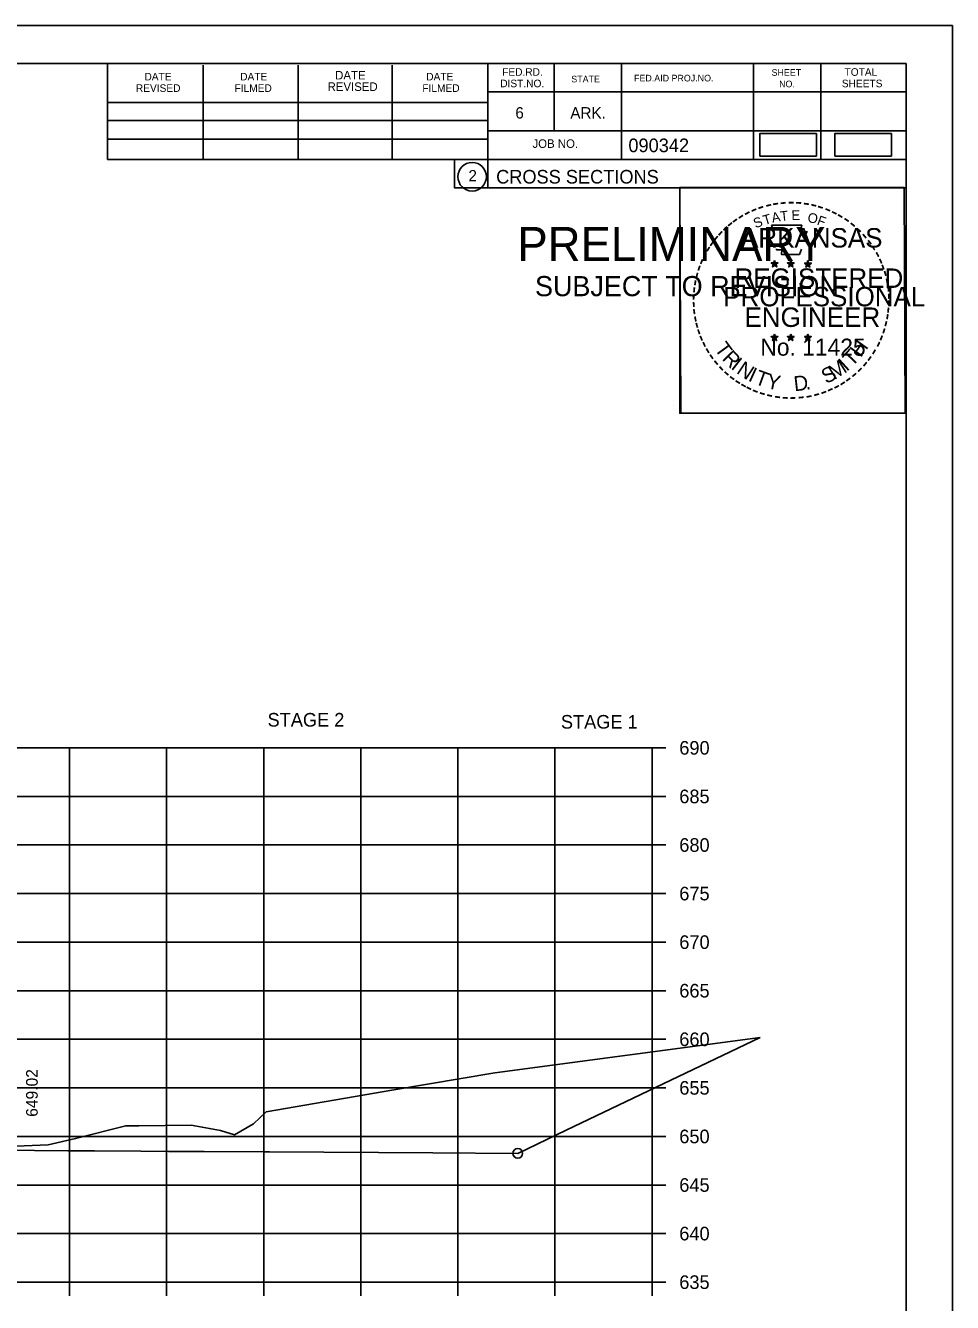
# Model space of a CAD drawing. Extents: x 1370515 to 1370849, y 383299 to 386073.
# Drawn here: x 1370753.3 to 1370848.7, y 384448 to 384579.5 of the extents above; entities that cross this region are included whole.
import ezdxf

# ---------------------------------------------------------------- set-up
doc = ezdxf.new("R2010")
doc.units = 0
for name, color, linetype in [('R_Axis', 7, 'Continuous'), ('R_Axis Annot', 7, 'Continuous'), ('R_Border', 7, 'Continuous'), ('R_Border PE', 7, 'Continuous'), ('R_Border Prem', 7, 'Continuous'), ('R_Detour', 7, 'Continuous'), ('R_Exist Surface', 7, 'Continuous'), ('R_Fin Surface', 7, 'Continuous'), ('R_Grid', 7, 'Continuous'), ('R_No Plot', 7, 'Continuous'), ('R_Xsect Elev', 7, 'Continuous')]:
    doc.layers.add(name, color=color, linetype=linetype)

msp = doc.modelspace()

# ---------------------------------------------------------------- linework, layer by layer
at = {"layer": 'R_Axis'}
for p, q in [((1370819.2, 384505.1), (1370816.4, 384505.1)), ((1370817.8, 384450.1), (1370817.8, 384505.1)), ((1370819.2, 384500.1), (1370816.4, 384500.1)), ((1370819.2, 384495.1), (1370816.4, 384495.1)), ((1370819.2, 384490.1), (1370816.4, 384490.1)), ((1370819.2, 384485.1), (1370816.4, 384485.1)), ((1370819.2, 384480.1), (1370816.4, 384480.1)), ((1370819.2, 384475.1), (1370816.4, 384475.1)), ((1370819.2, 384470.1), (1370816.4, 384470.1)), ((1370819.2, 384465.1), (1370816.4, 384465.1)), ((1370819.2, 384460.1), (1370816.4, 384460.1)), ((1370819.2, 384455.1), (1370816.4, 384455.1)), ((1370757.8, 384448.7), (1370757.8, 384451.5)), ((1370767.8, 384448.7), (1370767.8, 384451.5)), ((1370777.8, 384448.7), (1370777.8, 384451.5)), ((1370787.8, 384448.7), (1370787.8, 384451.5)), ((1370797.8, 384448.7), (1370797.8, 384451.5)), ((1370807.8, 384448.7), (1370807.8, 384451.5)), ((1370817.8, 384448.7), (1370817.8, 384451.5)), ((1370537.8, 384450.1), (1370817.8, 384450.1)), ((1370819.2, 384450.1), (1370816.4, 384450.1))]:
    msp.add_line(p, q, dxfattribs=at)
at = {"layer": 'R_Border'}
for p, q in [((1370527.8, 384575.56), (1370843.98, 384575.56)), ((1370761.72, 384565.68), (1370761.72, 384575.56)), ((1370771.58, 384565.68), (1370771.58, 384575.36)), ((1370781.34, 384565.68), (1370781.34, 384575.36)), ((1370791.02, 384565.68), (1370791.02, 384575.36)), ((1370800.88, 384575.56), (1370800.88, 384562.76)), ((1370807.72, 384575.56), (1370807.72, 384568.62)), ((1370814.66, 384575.56), (1370814.66, 384565.68)), ((1370828.24, 384575.56), (1370828.24, 384565.68)), ((1370835.18, 384575.56), (1370835.18, 384565.68)), ((1370843.98, 384370.1), (1370843.98, 384575.56)), ((1370843.98, 384572.62), (1370800.88, 384572.62)), ((1370843.98, 384572.64), (1370843.98, 384572.64)), ((1370761.72, 384571.54), (1370800.88, 384571.54)), ((1370761.72, 384569.68), (1370800.88, 384569.68)), ((1370761.72, 384565.68), (1370761.72, 384567.74)), ((1370761.72, 384567.74), (1370800.88, 384567.74)), ((1370843.98, 384568.62), (1370800.88, 384568.62)), ((1370803.84, 384568.62), (1370843.98, 384568.62)), ((1370843.98, 384565.68), (1370761.72, 384565.68)), ((1370800.88, 384562.76), (1370843.98, 384562.76))]:
    msp.add_line(p, q, dxfattribs=at)
msp.add_circle((1370799.27, 384563.89), 1.47, dxfattribs=at)
at = {"layer": 'R_Border PE'}
for p, q in [((1370830.07, 384555.01), (1370830.42, 384554.9)), ((1370830.07, 384555.01), (1370830.32, 384554.97)), ((1370830.07, 384555.01), (1370830.3, 384554.89)), ((1370830.2, 384554.61), (1370830.42, 384554.9)), ((1370830.2, 384554.61), (1370830.33, 384554.85)), ((1370830.2, 384554.61), (1370830.41, 384554.82)), ((1370830.42, 384555.27), (1370830.37, 384555.02)), ((1370830.63, 384554.61), (1370830.41, 384554.82)), ((1370830.42, 384554.9), (1370830.42, 384555.27)), ((1370830.42, 384555.27), (1370830.46, 384555.02)), ((1370830.76, 384555.01), (1370830.42, 384554.9)), ((1370830.63, 384554.61), (1370830.42, 384554.9)), ((1370830.76, 384555.01), (1370830.48, 384554.96)), ((1370830.63, 384554.61), (1370830.49, 384554.9)), ((1370830.76, 384555.01), (1370830.56, 384554.91)), ((1370831.74, 384555.01), (1370832.09, 384554.9)), ((1370831.74, 384555.01), (1370831.99, 384554.97)), ((1370831.74, 384555.01), (1370831.97, 384554.89)), ((1370831.87, 384554.61), (1370832.09, 384554.9)), ((1370831.87, 384554.61), (1370832, 384554.85)), ((1370831.87, 384554.61), (1370832.08, 384554.82)), ((1370832.09, 384555.27), (1370832.04, 384555.02)), ((1370832.3, 384554.61), (1370832.08, 384554.82)), ((1370832.09, 384554.9), (1370832.09, 384555.27)), ((1370832.09, 384555.27), (1370832.13, 384555.02)), ((1370832.43, 384555.01), (1370832.09, 384554.9)), ((1370832.3, 384554.61), (1370832.09, 384554.9)), ((1370832.43, 384555.01), (1370832.15, 384554.96)), ((1370832.3, 384554.61), (1370832.16, 384554.9)), ((1370832.43, 384555.01), (1370832.23, 384554.91)), ((1370833.5, 384555), (1370833.85, 384554.89)), ((1370833.5, 384555), (1370833.75, 384554.96)), ((1370833.5, 384555), (1370833.74, 384554.88)), ((1370833.63, 384554.59), (1370833.85, 384554.89)), ((1370833.63, 384554.59), (1370833.76, 384554.84)), ((1370833.63, 384554.59), (1370833.85, 384554.81)), ((1370833.85, 384555.26), (1370833.81, 384555)), ((1370833.85, 384554.89), (1370833.85, 384555.26)), ((1370833.85, 384555.26), (1370833.9, 384555.01)), ((1370834.2, 384555), (1370833.85, 384554.89)), ((1370834.06, 384554.59), (1370833.85, 384554.89)), ((1370834.06, 384554.59), (1370833.85, 384554.81)), ((1370834.2, 384555), (1370833.91, 384554.95)), ((1370834.06, 384554.59), (1370833.93, 384554.88)), ((1370834.2, 384555), (1370833.99, 384554.9)), ((1370830.06, 384547.44), (1370830.41, 384547.33)), ((1370830.06, 384547.44), (1370830.32, 384547.4)), ((1370830.06, 384547.44), (1370830.3, 384547.32)), ((1370830.2, 384547.03), (1370830.41, 384547.33)), ((1370830.2, 384547.03), (1370830.32, 384547.28)), ((1370830.2, 384547.03), (1370830.41, 384547.25)), ((1370830.41, 384547.69), (1370830.37, 384547.44)), ((1370830.41, 384547.33), (1370830.41, 384547.69)), ((1370830.41, 384547.69), (1370830.46, 384547.44)), ((1370830.76, 384547.44), (1370830.41, 384547.33)), ((1370830.62, 384547.03), (1370830.41, 384547.33)), ((1370830.62, 384547.03), (1370830.41, 384547.25)), ((1370830.76, 384547.44), (1370830.47, 384547.39)), ((1370830.62, 384547.03), (1370830.49, 384547.32)), ((1370830.76, 384547.44), (1370830.55, 384547.34)), ((1370831.73, 384547.44), (1370832.08, 384547.33)), ((1370831.73, 384547.44), (1370831.98, 384547.4)), ((1370831.73, 384547.44), (1370831.97, 384547.32)), ((1370831.86, 384547.03), (1370832.08, 384547.33)), ((1370831.86, 384547.03), (1370831.99, 384547.28)), ((1370831.86, 384547.03), (1370832.08, 384547.25)), ((1370832.08, 384547.69), (1370832.04, 384547.44)), ((1370832.08, 384547.33), (1370832.08, 384547.69)), ((1370832.08, 384547.69), (1370832.13, 384547.44)), ((1370832.43, 384547.44), (1370832.08, 384547.33)), ((1370832.29, 384547.03), (1370832.08, 384547.33)), ((1370832.29, 384547.03), (1370832.08, 384547.25)), ((1370832.43, 384547.44), (1370832.14, 384547.39)), ((1370832.29, 384547.03), (1370832.16, 384547.32)), ((1370832.43, 384547.44), (1370832.22, 384547.34)), ((1370833.5, 384547.43), (1370833.85, 384547.32)), ((1370833.5, 384547.43), (1370833.75, 384547.39)), ((1370833.5, 384547.43), (1370833.74, 384547.31)), ((1370833.63, 384547.02), (1370833.85, 384547.32)), ((1370833.63, 384547.02), (1370833.76, 384547.27)), ((1370833.63, 384547.02), (1370833.85, 384547.24)), ((1370833.85, 384547.68), (1370833.81, 384547.43)), ((1370833.85, 384547.32), (1370833.85, 384547.68)), ((1370833.85, 384547.68), (1370833.9, 384547.43)), ((1370834.19, 384547.43), (1370833.85, 384547.32)), ((1370834.06, 384547.02), (1370833.85, 384547.32)), ((1370834.06, 384547.02), (1370833.85, 384547.24)), ((1370834.19, 384547.43), (1370833.91, 384547.38)), ((1370834.06, 384547.02), (1370833.92, 384547.31)), ((1370834.19, 384547.43), (1370833.99, 384547.33))]:
    msp.add_line(p, q, dxfattribs=at)
for points in [[(1370830.11, 384558.89), (1370830.38, 384558.06)], [(1370833.62, 384557.97), (1370833.76, 384558.25), (1370833.08, 384558.23), (1370833.22, 384558.89), (1370830.11, 384558.89)], [(1370830.6, 384556.47), (1370830.6, 384556.38), (1370831.16, 384556.36), (1370831.11, 384555.89), (1370832.98, 384555.89), (1370833.18, 384556.43)], [(1370830.42, 384555.27), (1370830.63, 384554.61), (1370830.07, 384555.01), (1370830.76, 384555.01), (1370830.2, 384554.61), (1370830.42, 384555.27)], [(1370832.09, 384555.27), (1370832.3, 384554.61), (1370831.74, 384555.01), (1370832.43, 384555.01), (1370831.87, 384554.61), (1370832.09, 384555.27)], [(1370833.85, 384555.26), (1370834.06, 384554.59), (1370833.5, 384555), (1370834.2, 384555), (1370833.63, 384554.59), (1370833.85, 384555.26)], [(1370830.41, 384547.69), (1370830.62, 384547.03), (1370830.06, 384547.44), (1370830.76, 384547.44), (1370830.2, 384547.03), (1370830.41, 384547.69)], [(1370832.08, 384547.69), (1370832.29, 384547.03), (1370831.73, 384547.44), (1370832.43, 384547.44), (1370831.86, 384547.03), (1370832.08, 384547.69)], [(1370833.85, 384547.68), (1370834.06, 384547.02), (1370833.5, 384547.43), (1370834.19, 384547.43), (1370833.63, 384547.02), (1370833.85, 384547.68)]]:
    msp.add_lwpolyline(points, dxfattribs=at)
for centre, radius in [((1370830.41, 384554.9), 0.172), ((1370830.41, 384554.9), 0.145), ((1370830.41, 384554.9), 0.116), ((1370830.41, 384554.9), 0.0991), ((1370830.41, 384554.9), 0.0747), ((1370830.41, 384554.9), 0.0495), ((1370830.41, 384554.9), 0.0296), ((1370832.08, 384554.9), 0.172), ((1370832.08, 384554.9), 0.145), ((1370832.08, 384554.9), 0.116), ((1370832.08, 384554.9), 0.0991), ((1370832.08, 384554.9), 0.0747), ((1370832.08, 384554.9), 0.0495), ((1370832.08, 384554.9), 0.0296), ((1370833.85, 384554.89), 0.172), ((1370833.85, 384554.89), 0.145), ((1370833.85, 384554.89), 0.116), ((1370833.85, 384554.89), 0.0991), ((1370833.85, 384554.89), 0.0747), ((1370833.85, 384554.89), 0.0495), ((1370833.85, 384554.89), 0.0296), ((1370830.41, 384547.33), 0.172), ((1370830.41, 384547.33), 0.145), ((1370830.41, 384547.33), 0.116), ((1370830.41, 384547.33), 0.0991), ((1370830.41, 384547.33), 0.0747), ((1370830.41, 384547.33), 0.0495), ((1370830.41, 384547.33), 0.0296), ((1370832.08, 384547.33), 0.172), ((1370832.08, 384547.33), 0.145), ((1370832.08, 384547.33), 0.116), ((1370832.08, 384547.33), 0.0991), ((1370832.08, 384547.33), 0.0747), ((1370832.08, 384547.33), 0.0495), ((1370832.08, 384547.33), 0.0296), ((1370833.85, 384547.32), 0.172), ((1370833.85, 384547.32), 0.145), ((1370833.85, 384547.32), 0.116), ((1370833.85, 384547.32), 0.0991), ((1370833.85, 384547.32), 0.0747), ((1370833.85, 384547.32), 0.0495), ((1370833.85, 384547.32), 0.0296)]:
    msp.add_circle(centre, radius, dxfattribs=at)
at = {"layer": 'R_Detour'}
for points in [[(1370828.89, 384566.02), (1370834.73, 384566.02), (1370834.73, 384568.33), (1370828.89, 384568.33)], [(1370836.61, 384566.02), (1370842.45, 384566.02), (1370842.45, 384568.33), (1370836.61, 384568.33)]]:
    msp.add_lwpolyline(points, close=True, dxfattribs=at)
at = {"layer": 'R_Exist Surface'}
msp.add_lwpolyline([(1370747.33, 384463.89), (1370755.59, 384464.24), (1370758.43, 384464.88), (1370763.6, 384466.2), (1370764.93, 384466.2), (1370770.33, 384466.25), (1370773.37, 384465.7), (1370774.79, 384465.27), (1370776.76, 384466.39), (1370778.04, 384467.63), (1370791.22, 384469.88), (1370801.6, 384471.63), (1370828.92, 384475.28)], dxfattribs=at)
at = {"layer": 'R_Fin Surface'}
msp.add_lwpolyline([(1370747.31, 384463.73), (1370757.64, 384463.63), (1370757.72, 384463.63), (1370760.37, 384463.61), (1370765.16, 384463.58), (1370768.01, 384463.56), (1370771.67, 384463.54), (1370777.8, 384463.5), (1370778.17, 384463.5), (1370778.39, 384463.5), (1370795.23, 384463.4), (1370803.97, 384463.35), (1370808.96, 384465.74), (1370828.92, 384475.28)], dxfattribs=at)
at = {"layer": 'R_Grid'}
for p, q in [((1370537.8, 384505.1), (1370817.8, 384505.1)), ((1370757.8, 384450.1), (1370757.8, 384505.1)), ((1370767.8, 384450.1), (1370767.8, 384505.1)), ((1370777.8, 384450.1), (1370777.8, 384505.1)), ((1370787.8, 384450.1), (1370787.8, 384505.1)), ((1370797.8, 384450.1), (1370797.8, 384505.1)), ((1370807.8, 384450.1), (1370807.8, 384505.1)), ((1370817.8, 384450.1), (1370817.8, 384505.1)), ((1370537.8, 384500.1), (1370817.8, 384500.1)), ((1370537.8, 384495.1), (1370817.8, 384495.1)), ((1370537.8, 384490.1), (1370817.8, 384490.1)), ((1370537.8, 384485.1), (1370817.8, 384485.1)), ((1370537.8, 384480.1), (1370817.8, 384480.1)), ((1370537.8, 384475.1), (1370817.8, 384475.1)), ((1370537.8, 384470.1), (1370817.8, 384470.1)), ((1370537.8, 384465.1), (1370817.8, 384465.1)), ((1370537.8, 384460.1), (1370817.8, 384460.1)), ((1370537.8, 384455.1), (1370817.8, 384455.1)), ((1370537.8, 384450.1), (1370817.8, 384450.1))]:
    msp.add_line(p, q, dxfattribs=at)
at = {"layer": 'R_No Plot'}
for p, q in [((1370515.4, 384579.45), (1370848.73, 384579.45)), ((1370820.02, 384540.3), (1370820.02, 384540.3))]:
    msp.add_line(p, q, dxfattribs=at)
for points in [[(1370515.39, 384579.45), (1370848.73, 384579.45), (1370848.73, 384366.12), (1370515.39, 384366.12)], [(1370761.72, 384575.56), (1370761.72, 384565.68), (1370797.45, 384565.68), (1370797.45, 384562.76), (1370820.65, 384562.76), (1370820.65, 384539.54), (1370843.98, 384539.54), (1370843.98, 384370.1), (1370527.8, 384370.1), (1370527.8, 384575.56)], [(1370820.65, 384562.79), (1370843.75, 384562.79), (1370843.87, 384539.54), (1370820.77, 384539.54)]]:
    msp.add_lwpolyline(points, close=True, dxfattribs=at)
msp.add_circle((1370803.97, 384463.35), 0.5, dxfattribs=at)
msp.add_circle((1370803.97, 384463.35), 0.5, dxfattribs=at)

# ---------------------------------------------------------------- texts
at = {"layer": 'R_Axis Annot'}
for s, p in [('STAGE 2', (1370778.2, 384507.29)), ('STAGE 1', (1370808.41, 384507.08)), ('690', (1370820.6, 384504.4)), ('685', (1370820.6, 384499.4)), ('680', (1370820.6, 384494.4)), ('675', (1370820.6, 384489.4)), ('670', (1370820.6, 384484.4)), ('665', (1370820.6, 384479.4)), ('660', (1370820.6, 384474.4)), ('655', (1370820.6, 384469.4)), ('650', (1370820.6, 384464.4)), ('645', (1370820.6, 384459.4)), ('640', (1370820.6, 384454.4)), ('635', (1370820.6, 384449.4))]:
    msp.add_text(s, height=1.4, dxfattribs=at).set_placement(p)
at = {"layer": 'R_Border'}
for s, height, p in [('DATE', 0.782, (1370765.52, 384573.8)), ('DATE', 0.782, (1370775.38, 384573.8)), ('DATE', 0.879, (1370785.16, 384573.9)), ('DATE', 0.782, (1370794.54, 384573.8)), ('FED.RD.', 0.782, (1370802.36, 384574.28)), ('STATE', 0.684, (1370809.48, 384573.6)), ('FED.AID PROJ.NO.', 0.684, (1370815.94, 384573.7)), ('SHEET', 0.684, (1370830.1, 384574.28)), ('TOTAL', 0.782, (1370837.62, 384574.28)), ('REVISED', 0.782, (1370764.64, 384572.62)), ('FILMED', 0.782, (1370774.8, 384572.62)), ('REVISED', 0.879, (1370784.38, 384572.72)), ('FILMED', 0.782, (1370794.14, 384572.62)), ('DIST.NO.', 0.782, (1370802.16, 384573.1)), ('NO.', 0.684, (1370830.88, 384573.1)), ('SHEETS', 0.782, (1370837.34, 384573.1)), ('6', 1.17, (1370803.72, 384569.88)), ('ARK.', 1.172, (1370809.38, 384569.88)), ('JOB NO.', 0.879, (1370805.48, 384566.86)), ('090342', 1.4, (1370815.36, 384566.42)), ('2', 1.17, (1370798.89, 384563.41)), ('CROSS SECTIONS', 1.4, (1370801.74, 384563.19))]:
    msp.add_text(s, height=height, rotation=360, dxfattribs=at).set_placement(p)
at = {"layer": 'R_Border PE'}
for s, height, rotation, p in [('-', 1.6, 10.2193, (1370830.28, 384560.42)), ('-', 1.6, 5.8968, (1370831.01, 384560.53)), ('-', 1.6, 0.1862, (1370831.78, 384560.6)), ('-', 1.6, 357.743, (1370832.51, 384560.59)), ('-', 1.6, 352.1617, (1370833.25, 384560.53)), ('-', 1.6, 34.0636, (1370826.99, 384559.06)), ('-', 1.6, 28.7918, (1370827.59, 384559.43)), ('-', 1.6, 24.3072, (1370828.22, 384559.75)), ('-', 1.6, 19.1761, (1370828.86, 384560.02)), ('T', 1, 16.4036, (1370829.38, 384558.9)), ('-', 1.6, 13.6301, (1370829.61, 384560.26)), ('A', 1, 11.2132, (1370830.2, 384559.15)), ('T', 1, 6.0228, (1370831.05, 384559.32)), ('E', 1, 0.8323, (1370832.16, 384559.43)), ('O', 1, 350.4515, (1370833.76, 384559.22)), ('-', 1.6, 347.2049, (1370833.97, 384560.42)), ('F', 1, 340.0707, (1370834.71, 384558.99)), ('-', 1.6, 342.3362, (1370834.61, 384560.27)), ('-', 1.6, 337.8551, (1370835.34, 384560.04)), ('-', 1.6, 334.1211, (1370835.97, 384559.77)), ('-', 1.6, 329.6409, (1370836.55, 384559.49)), ('-', 1.6, 42.9622, (1370825.5, 384557.87)), ('-', 1.6, 38.9507, (1370825.94, 384558.29)), ('-', 1.6, 36.2317, (1370826.41, 384558.67)), ('ARKANSAS', 2, 360, (1370826.96, 384556.6)), ('S', 1, 21.594, (1370828.46, 384558.57)), ('-', 1.6, 325.8627, (1370837.19, 384559.13)), ('-', 1.6, 320.5297, (1370837.8, 384558.7)), ('-', 1.6, 315.5786, (1370838.4, 384558.21)), ('-', 1.6, 54.2325, (1370824.24, 384556.34)), ('-', 1.6, 50.6142, (1370824.65, 384556.91)), ('-', 1.6, 48.423, (1370825.06, 384557.39)), ('-', 1.6, 309.8797, (1370838.97, 384557.66)), ('-', 1.6, 306.6522, (1370839.5, 384557.06)), ('-', 1.6, 62.8713, (1370823.6, 384555.2)), ('-', 1.6, 58.0706, (1370823.92, 384555.81)), ('-', 1.4, 303.6753, (1370839.98, 384556.49)), ('-', 1.6, 299.6684, (1370840.3, 384555.89)), ('-', 1.6, 72.3945, (1370823.12, 384553.96)), ('-', 1.6, 67.7743, (1370823.34, 384554.59)), ('DWB', 0.01, 360, (1370830.4, 384554.9)), ('DWB', 0.01, 360, (1370832.07, 384554.9)), ('DWB', 0.01, 360, (1370833.84, 384554.89)), ('-', 1.6, 294.6628, (1370840.63, 384555.27)), ('-', 1.6, 290.5728, (1370840.88, 384554.7)), ('-', 1.6, 81.2013, (1370822.8, 384552.53)), ('-', 1.6, 75.461, (1370822.93, 384553.25)), ('REGISTERED', 2, 360, (1370826.28, 384552.45)), ('-', 1.6, 285.1233, (1370841.12, 384554.12)), ('-', 1.6, 280.5493, (1370841.32, 384553.38)), ('-', 1.6, 85.1863, (1370822.72, 384551.84)), ('PROFESSIONAL', 2, 360, (1370825.13, 384550.55)), ('-', 1.6, 276.5962, (1370841.48, 384552.61)), ('-', 1.6, 94.1959, (1370822.73, 384550.42)), ('-', 1.6, 89.0622, (1370822.69, 384551.14)), ('-', 1.6, 274.3301, (1370841.54, 384551.89)), ('-', 1.6, 269.9407, (1370841.57, 384551.25)), ('-', 1.6, 98.9479, (1370822.8, 384549.75)), ('-', 1.6, 101.7149, (1370822.94, 384549.02)), ('ENGINEER', 2, 360, (1370827.32, 384548.43)), ('-', 1.6, 260.9953, (1370841.48, 384549.93)), ('-', 1.6, 263.5172, (1370841.55, 384550.59)), ('-', 1.6, 105.4578, (1370823.1, 384548.42)), ('-', 1.6, 109.0874, (1370823.31, 384547.79)), ('-', 1.6, 252.8681, (1370841.19, 384548.54)), ('-', 1.6, 255.7626, (1370841.37, 384549.26)), ('-', 1.6, 114.0643, (1370823.57, 384547.19)), ('-', 1.6, 115.7288, (1370823.87, 384546.58)), ('T', 1.54, 306.0406, (1370824.17, 384546.17)), ('No. 11425', 1.757, 360, (1370828.95, 384545.47)), ('DWB', 0.01, 360, (1370830.4, 384547.32)), ('DWB', 0.01, 360, (1370832.07, 384547.33)), ('DWB', 0.01, 360, (1370833.83, 384547.32)), ('H', 1.54, 54.6088, (1370839.29, 384545.2)), ('-', 1.6, 244.6197, (1370840.71, 384547.23)), ('-', 1.6, 247.8887, (1370840.97, 384547.86)), ('-', 1.6, 120.4471, (1370824.23, 384545.99)), ('-', 1.6, 125.8934, (1370824.63, 384545.43)), ('R', 1.54, 314.005, (1370824.93, 384545.12)), ('T', 1.54, 46.6444, (1370838.4, 384544.26)), ('-', 1.6, 233.8452, (1370839.91, 384545.83)), ('-', 1.6, 239.0712, (1370840.31, 384546.48)), ('-', 1.6, 130.7181, (1370825.09, 384544.88)), ('-', 1.6, 134.2238, (1370825.61, 384544.33)), ('I', 1.54, 321.9694, (1370825.83, 384544.19)), ('N', 1.54, 326.5002, (1370826.4, 384543.72)), ('I', 1.54, 335.3603, (1370827.61, 384542.93)), ('T', 1.54, 339.8912, (1370828.27, 384542.6)), ('S', 1.54, 26.9312, (1370835.72, 384542.53)), ('M', 1.54, 32.6563, (1370836.56, 384542.94)), ('I', 1.54, 42.1136, (1370837.84, 384543.78)), ('-', 1.6, 225.7653, (1370839, 384544.7)), ('-', 1.6, 231.2538, (1370839.48, 384545.26)), ('-', 1.6, 138.9338, (1370826.14, 384543.87)), ('-', 1.6, 144.6463, (1370826.69, 384543.46)), ('-', 1.6, 148.0898, (1370827.25, 384543.09)), ('Y', 1.54, 347.8556, (1370829.49, 384542.16)), ('D', 1.54, 6.3969, (1370832.47, 384541.8)), ('-', 1.6, 212.2491, (1370837.4, 384543.33)), ('-', 1.6, 215.7363, (1370837.93, 384543.72)), ('-', 1.6, 221.0851, (1370838.48, 384544.19)), ('-', 1.6, 151.5704, (1370827.83, 384542.77)), ('-', 1.6, 154.6002, (1370828.35, 384542.52)), ('-', 1.6, 158.5612, (1370828.98, 384542.26)), ('-', 1.6, 162.7983, (1370829.67, 384542.05)), ('-', 1.6, 167.5555, (1370830.38, 384541.89)), ('-', 1.6, 191.2858, (1370834.19, 384541.95)), ('.', 1.54, 13.7642, (1370833.66, 384541.93)), ('-', 1.6, 195.4743, (1370834.92, 384542.15)), ('-', 1.6, 200.7184, (1370835.6, 384542.39)), ('-', 1.6, 204.2516, (1370836.21, 384542.67)), ('-', 1.6, 207.3568, (1370836.84, 384542.98)), ('-', 1.6, 173.1155, (1370831.15, 384541.78)), ('-', 1.6, 176.5183, (1370831.9, 384541.72)), ('-', 1.6, 181.5918, (1370832.64, 384541.74)), ('-', 1.6, 185.8167, (1370833.45, 384541.82))]:
    msp.add_text(s, height=height, rotation=rotation, dxfattribs=at).set_placement(p)
at = {"layer": 'R_Border Prem'}
for s, height, p in [('PRELIMINARY', 3.5, (1370803.93, 384555.22)), ('DWB', 0.01, (1370804.68, 384557.07)), ('SUBJECT TO REVISION', 2.0751, (1370805.74, 384551.59))]:
    msp.add_text(s, height=height, rotation=360, dxfattribs=at).set_placement(p)
at = {"layer": 'R_No Plot'}
for p in [(1370778, 384467.58), (1370763.56, 384466.15), (1370770.29, 384466.2), (1370774.75, 384465.22), (1370755.55, 384464.19)]:
    msp.add_text('+', height=0.1, dxfattribs=at).set_placement(p)
at = {"layer": 'R_Xsect Elev'}
msp.add_text('649.02', height=1.2, rotation=90, dxfattribs=at).set_placement((1370754.53, 384467.12))

doc.saveas('drawing.dxf')
